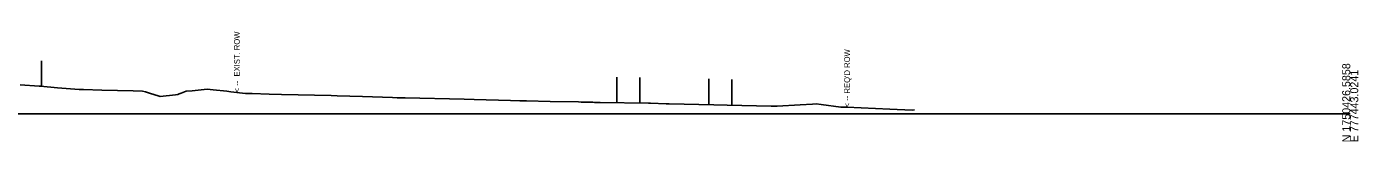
# Model space of a CAD drawing. Extents: x 776426 to 854588, y 1736205 to 1756790.
# Drawn here: x 805207.6 to 805673.6, y 1750705.1 to 1750743.5 of the extents above; entities that cross this region are included whole.
import ezdxf

# ---------------------------------------------------------------- set-up
doc = ezdxf.new("R2010")
doc.units = 0
for name, color, linetype in [('63', 7, 'Continuous'), ('DTM CONTOURS_MAJOR_TX', 7, 'Continuous'), ('DTM_X_FLOW_ARROWS', 7, 'Continuous'), ('TRANS_EOP_PAVED', 7, 'Continuous'), ('TRANS_UNPAVED_SHOULDERS', 7, 'Continuous'), ('XS_P_ROW', 7, 'Continuous'), ('XS_X_ROW', 7, 'Continuous')]:
    doc.layers.add(name, color=color, linetype=linetype)

msp = doc.modelspace()

# ---------------------------------------------------------------- linework, layer by layer
at = {"layer": '63'}
msp.add_line((805212.79, 1750733.35), (805212.79, 1750724.35), dxfattribs=at)
msp.add_line((805212.79, 1750733.35), (805212.79, 1750724.35), dxfattribs=at)
at = {"layer": 'DTM CONTOURS_MAJOR_TX'}
msp.add_line((805170.79, 1750714.76), (805670.79, 1750714.76), dxfattribs=at)
at = {"layer": 'DTM_X_FLOW_ARROWS'}
msp.add_lwpolyline([(805205.4, 1750724.95), (805212.02, 1750724.41), (805212.53, 1750724.37), (805218.41, 1750723.9), (805226.06, 1750723.29), (805226.51, 1750723.28), (805227.53, 1750723.25), (805233.99, 1750723.07), (805244.94, 1750722.79), (805248.16, 1750722.73), (805249.23, 1750722.43), (805250.58, 1750721.99), (805253.99, 1750720.93), (805254.35, 1750720.84), (805259.73, 1750721.41), (805260.53, 1750721.51), (805260.95, 1750721.72), (805261.32, 1750721.81), (805261.66, 1750721.98), (805263.5, 1750722.68), (805265.52, 1750722.83), (805270.78, 1750723.36), (805272.95, 1750723.17), (805277.73, 1750722.65), (805279.07, 1750722.49), (805284.17, 1750721.89), (805286.51, 1750721.83), (805292.49, 1750721.65), (805296.86, 1750721.55), (805314.24, 1750721.16), (805316.26, 1750721.08), (805325.16, 1750720.76), (805335.6, 1750720.43), (805337.28, 1750720.38), (805340.04, 1750720.3), (805360.77, 1750719.9), (805364.28, 1750719.79), (805376.94, 1750719.44), (805380.16, 1750719.34), (805380.5, 1750719.33), (805382.58, 1750719.26), (805390.78, 1750719.08), (805400.68, 1750718.89), (805401.72, 1750718.86), (805405.11, 1750718.78), (805405.79, 1750718.77), (805406.38, 1750718.75), (805406.82, 1750718.72), (805407.47, 1750718.74), (805408.33, 1750718.73), (805425.23, 1750718.45), (805425.94, 1750718.45), (805431.37, 1750718.27), (805432.43, 1750718.28), (805448.09, 1750717.91), (805452.77, 1750717.83), (805468.19, 1750717.43), (805469.32, 1750717.43), (805470.3, 1750717.38), (805478.31, 1750717.87), (805482.58, 1750718.12), (805483.9, 1750718.19), (805485.64, 1750717.95), (805492.51, 1750717.05), (805494.65, 1750717.02), (805509.73, 1750716.41), (805517.49, 1750716.02), (805518.33, 1750716.14)], dxfattribs=at)
at = {"layer": 'TRANS_EOP_PAVED'}
for p, q in [((805422.22, 1750727.5), (805422.22, 1750718.5)), ((805422.22, 1750727.5), (805422.22, 1750718.5)), ((805446.38, 1750726.95), (805446.38, 1750717.95)), ((805446.38, 1750726.95), (805446.38, 1750717.95))]:
    msp.add_line(p, q, dxfattribs=at)
at = {"layer": 'TRANS_UNPAVED_SHOULDERS'}
for p, q in [((805414.16, 1750727.63), (805414.16, 1750718.63)), ((805414.16, 1750727.63), (805414.16, 1750718.63)), ((805454.44, 1750726.79), (805454.44, 1750717.79)), ((805454.44, 1750726.79), (805454.44, 1750717.79))]:
    msp.add_line(p, q, dxfattribs=at)

# ---------------------------------------------------------------- texts
at = {"layer": 'DTM CONTOURS_MAJOR_TX'}
for s, p in [('N 1750426.5858', (805670.79, 1750704.76)), ('E 777443.0241', (805673.59, 1750704.76))]:
    msp.add_text(s, height=2.8, rotation=90, dxfattribs=at).set_placement(p)
at = {"layer": 'XS_P_ROW'}
msp.add_text("< -- REQ'D ROW", height=2, rotation=90, dxfattribs=at).set_placement((805495.71, 1750717.02))
at = {"layer": 'XS_X_ROW'}
msp.add_text('< --  EXIST. ROW', height=2, rotation=90, dxfattribs=at).set_placement((805282.21, 1750722.24))

doc.saveas('drawing.dxf')
